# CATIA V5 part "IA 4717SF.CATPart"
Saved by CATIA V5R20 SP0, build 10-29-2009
Part number: IA 4717SF
Revision: ANY
Definition: UNKNOWN
Nomenclature: IA 4717SF
Source: Unknown
Bounding box of the stored display mesh (mm): x -2.35 to 2.35, y -7.925 to 9.045, z -2.35 to 2.35
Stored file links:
  C:\Users\Utente\Desktop\IO LAVORO\3D X SITO CF\CUMSA\3D files FA\FA 0847SF\IA 4717SF.CATPart

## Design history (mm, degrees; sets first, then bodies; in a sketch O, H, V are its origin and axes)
Body1 "Cortar-Extruir2" (main body)
  Solid1: solid without history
